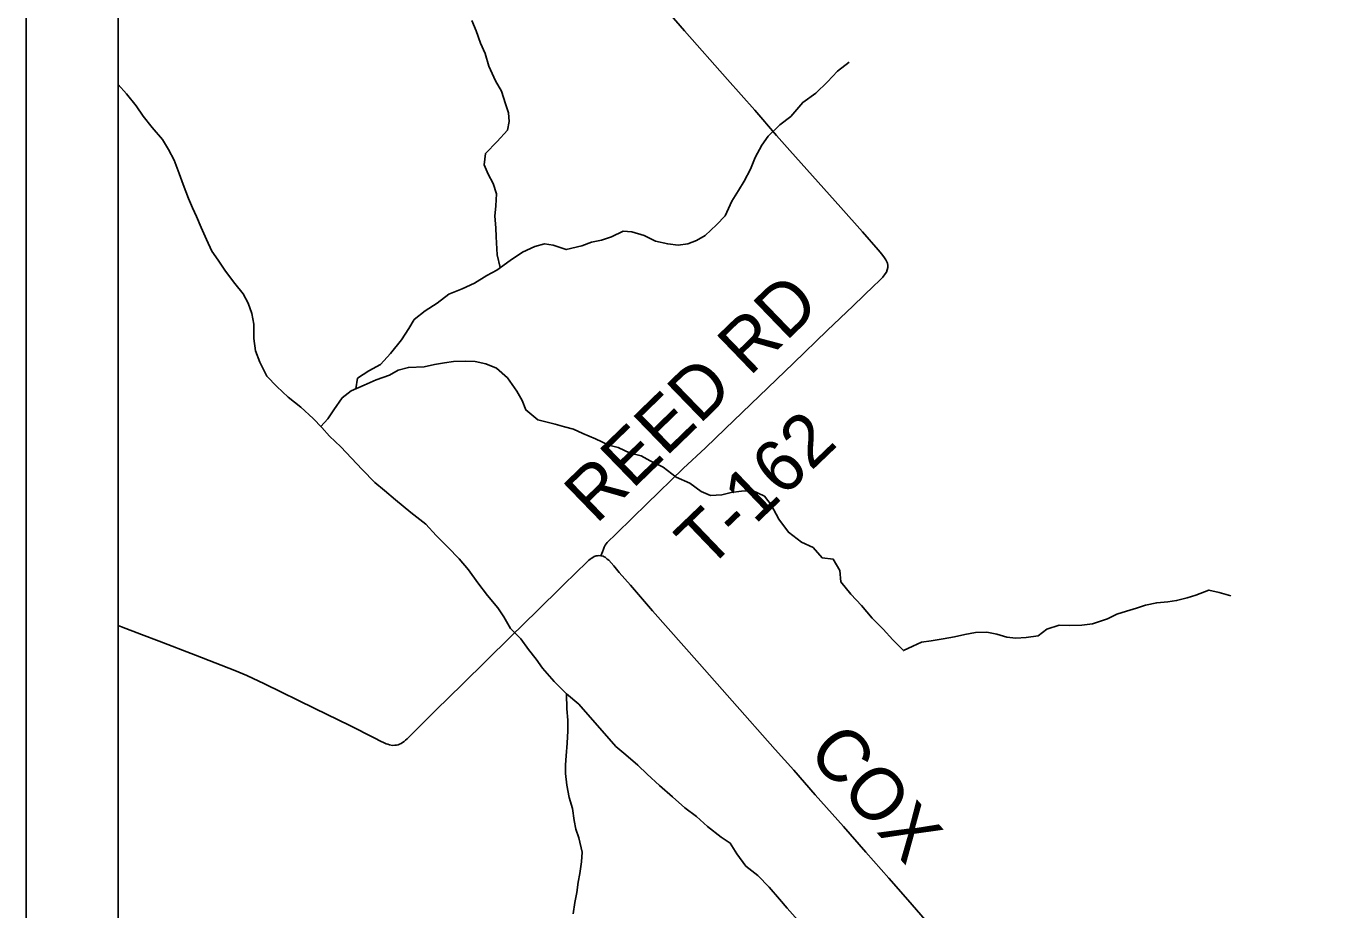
# Model space of a CAD drawing. Extents: x 0 to 34, y 0 to 22.
# Drawn here: x 2 to 3.432, y 19.235 to 20.196 of the extents above; entities that cross this region are included whole.
import ezdxf

# ---------------------------------------------------------------- set-up
doc = ezdxf.new("R2010")
doc.units = 0
for name, color, linetype in [('Default', 7, 'Continuous'), ('GM_X_County_Road', 7, 'Continuous'), ('GM_X_County_Road_Text', 7, 'Continuous'), ('GM_X_Major_River', 7, 'Continuous'), ('GM_X_Minor_River', 7, 'Continuous'), ('GM_X_Township_Road', 7, 'Continuous'), ('GM_X_Township_Road_Text', 7, 'Continuous'), ('SH_Cut_Line', 7, 'Continuous'), ('SH_Data', 7, 'Continuous')]:
    doc.layers.add(name, color=color, linetype=linetype)

msp = doc.modelspace()

# ---------------------------------------------------------------- linework, layer by layer
at = {"layer": 'Default'}
msp.add_lwpolyline([(6.6858, 19.0362), (6.6949, 19.1537), (6.8302, 20.9), (3.1229, 20.9), (2.9275, 20.8467), (2.2946, 20.6707), (2.1, 20.6202), (2.1, 17.1279), (2.1211, 17.1003), (3.2076, 15.5689), (3.4902, 15.1704), (4.0558, 14.3671), (4.1658, 14.2105), (4.302, 14.3105), (5.6165, 15.2674), (6.0871, 15.6176), (6.2834, 15.7529), (6.4392, 15.8657), (6.5428, 17.1931), (6.5451, 17.2211), (6.6309, 18.3364), (6.6363, 18.3979), (6.6654, 18.7733)], dxfattribs=at)
at = {"layer": 'GM_X_County_Road'}
for points in [[(2.6248, 19.6198), (2.6226, 19.62), (2.6211, 19.6199), (2.6199, 19.6197), (2.6188, 19.6194), (2.6177, 19.6189), (2.616, 19.618), (2.6142, 19.6168), (2.6132, 19.6161), (2.6119, 19.615), (2.6101, 19.6134), (2.6073, 19.6108), (2.5998, 19.6034), (2.5821, 19.5859), (2.556, 19.5602), (2.5265, 19.5317), (2.5004, 19.5059), (2.4743, 19.4802), (2.4454, 19.452), (2.4182, 19.4247), (2.4142, 19.4207), (2.4123, 19.4191), (2.4108, 19.4178), (2.409, 19.4167), (2.4075, 19.4157), (2.4058, 19.4149), (2.4043, 19.4143), (2.4027, 19.4139), (2.4008, 19.4136), (2.3982, 19.4135), (2.3949, 19.4141), (2.393, 19.4147), (2.3913, 19.4153), (2.3886, 19.4166), (2.3861, 19.4178), (2.3784, 19.4217), (2.3517, 19.435), (2.3138, 19.4538), (2.2592, 19.4806), (2.24, 19.4895), (2.2269, 19.4949), (2.1841, 19.5118), (2.1446, 19.5268), (2.1254, 19.534), (2.1034, 19.5426), (2.1, 19.5439)], [(2.9823, 19.2184), (2.9586, 19.2455), (2.9382, 19.2689), (2.9131, 19.2974), (2.8886, 19.3254), (2.8581, 19.3599), (2.8346, 19.3864), (2.8144, 19.4091), (2.7675, 19.4621), (2.732, 19.5021), (2.6811, 19.56), (2.6571, 19.5877), (2.6449, 19.6018), (2.6389, 19.6089), (2.6336, 19.6149), (2.6319, 19.6163), (2.6308, 19.6172), (2.6294, 19.6182), (2.6285, 19.6186), (2.6273, 19.6193), (2.6261, 19.6196), (2.6248, 19.6198)]]:
    msp.add_lwpolyline(points, dxfattribs=at)
at = {"layer": 'GM_X_Major_River'}
msp.add_lwpolyline([(2.1, 20.1327), (2.1089, 20.1225), (2.1195, 20.1092), (2.127, 20.0981), (2.1368, 20.0859), (2.1481, 20.0726), (2.1545, 20.0619), (2.1609, 20.0501), (2.1662, 20.0357), (2.1706, 20.0239), (2.1763, 20.0087), (2.1808, 19.9984), (2.1849, 19.9889), (2.1901, 19.9771), (2.1958, 19.9638), (2.2018, 19.9512), (2.2085, 19.9413), (2.2165, 19.9295), (2.2266, 19.9162), (2.2357, 19.9047), (2.2413, 19.8945), (2.2454, 19.8834), (2.2473, 19.872), (2.2476, 19.8561), (2.2494, 19.8428), (2.2539, 19.8303), (2.2614, 19.8154), (2.2724, 19.804), (2.2848, 19.7925), (2.2984, 19.7815), (2.312, 19.7692), (2.3215, 19.7593), (2.3298, 19.7498), (2.3419, 19.7383), (2.3536, 19.7261), (2.3653, 19.7136), (2.3789, 19.6994), (2.3894, 19.6907), (2.4015, 19.6807), (2.4182, 19.667), (2.4344, 19.6544), (2.4458, 19.6418), (2.4586, 19.6292), (2.4707, 19.6166), (2.4809, 19.6044), (2.491, 19.5903), (2.5016, 19.5766), (2.5129, 19.5633), (2.5193, 19.5534), (2.5265, 19.5408), (2.5378, 19.5294), (2.5461, 19.5179), (2.5544, 19.5073), (2.5615, 19.4977), (2.574, 19.4832), (2.5876, 19.4695), (2.6008, 19.4584)], dxfattribs=at)
at = {"layer": 'GM_X_Minor_River'}
for points in [[(2.5154, 19.9333), (2.5121, 19.9472), (2.5109, 19.967), (2.5106, 19.9765), (2.5096, 19.9895), (2.5105, 20.0005), (2.5114, 20.0137), (2.5078, 20.0248), (2.5022, 20.0351), (2.4981, 20.0451), (2.4994, 20.0576), (2.5121, 20.0704), (2.5233, 20.0828), (2.5253, 20.0922), (2.5243, 20.1018), (2.5213, 20.1117), (2.5169, 20.1254), (2.5102, 20.1365), (2.5032, 20.1525), (2.4992, 20.1663), (2.494, 20.1777), (2.4892, 20.1911), (2.4844, 20.2021)], [(2.3584, 19.8016), (2.3603, 19.8129), (2.3725, 19.8211), (2.3852, 19.8278), (2.396, 19.8399), (2.4079, 19.8546), (2.4161, 19.867), (2.4219, 19.8768), (2.4338, 19.8862), (2.4468, 19.8948), (2.4595, 19.9045), (2.474, 19.9101), (2.4874, 19.9164), (2.5008, 19.9246), (2.5116, 19.9305), (2.5261, 19.941), (2.5396, 19.95), (2.553, 19.9563), (2.5637, 19.9592), (2.5731, 19.9576), (2.5872, 19.9529), (2.604, 19.9572), (2.6147, 19.9609), (2.6257, 19.9631), (2.6364, 19.9667), (2.649, 19.9731), (2.6585, 19.9722), (2.6718, 19.9682), (2.6843, 19.962), (2.6976, 19.9592), (2.709, 19.9579), (2.7193, 19.9594), (2.7288, 19.9627), (2.7384, 19.9683), (2.7507, 19.9799), (2.76, 19.9897), (2.7674, 20.0055), (2.7747, 20.0172), (2.7806, 20.0274), (2.7876, 20.0403), (2.7927, 20.0531), (2.8001, 20.0664), (2.807, 20.0762), (2.8194, 20.0886), (2.8313, 20.0979), (2.8444, 20.113), (2.8586, 20.1231), (2.8713, 20.1355), (2.8821, 20.1471), (2.8951, 20.1569)], [(2.3204, 19.7605), (2.3278, 19.7688), (2.3344, 19.7786), (2.3436, 19.7918), (2.3532, 19.7993), (2.3674, 19.8056), (2.3804, 19.8112), (2.3949, 19.8163), (2.4045, 19.8219), (2.4156, 19.8248), (2.4327, 19.8254), (2.4441, 19.8279), (2.4548, 19.8297), (2.4647, 19.8311), (2.4777, 19.8314), (2.4883, 19.8312), (2.4997, 19.8288), (2.5114, 19.8241), (2.5235, 19.8134), (2.5336, 19.7988), (2.5392, 19.7889), (2.5432, 19.7786), (2.5564, 19.7678), (2.575, 19.763), (2.5852, 19.7602), (2.5951, 19.7575), (2.6053, 19.7528), (2.6189, 19.7469), (2.6337, 19.7403), (2.6436, 19.7375), (2.6568, 19.7313), (2.6686, 19.7285), (2.6784, 19.7231), (2.6928, 19.7161), (2.7067, 19.7053), (2.7215, 19.6987), (2.7339, 19.6898), (2.7441, 19.6855), (2.7563, 19.6861), (2.7666, 19.6887), (2.7777, 19.6901), (2.7899, 19.6907), (2.8027, 19.6848), (2.8102, 19.6752), (2.8184, 19.6596), (2.8289, 19.6454), (2.8432, 19.6346), (2.8557, 19.6288), (2.8655, 19.6176), (2.8776, 19.616), (2.8847, 19.6037), (2.8857, 19.5916), (2.8966, 19.5781), (2.9082, 19.5659), (2.9198, 19.552), (2.9319, 19.5401), (2.9424, 19.5282), (2.954, 19.5167), (2.964, 19.5215), (2.9735, 19.526), (2.9842, 19.5274), (2.9972, 19.5295), (3.0094, 19.5317), (3.0208, 19.5342), (3.0323, 19.5363), (3.0448, 19.5366), (3.0555, 19.5346), (3.0664, 19.5314), (3.0763, 19.5301), (3.0874, 19.5308), (3.1003, 19.5329), (3.1099, 19.54), (3.1233, 19.5444), (3.1343, 19.5439), (3.148, 19.5442), (3.1595, 19.5459), (3.1759, 19.5514), (3.1862, 19.5563), (3.1965, 19.5596), (3.2076, 19.5629), (3.2171, 19.5662), (3.2294, 19.5687), (3.2415, 19.5697), (3.2511, 19.5711), (3.2625, 19.574), (3.2721, 19.577), (3.2862, 19.5825), (3.2972, 19.5797), (3.3101, 19.5761)], [(2.5876, 19.4695), (2.588, 19.4532), (2.589, 19.441), (2.5889, 19.4292), (2.5883, 19.416), (2.587, 19.4023), (2.5865, 19.3924), (2.5864, 19.3829), (2.5878, 19.3704), (2.5903, 19.3567), (2.594, 19.3448), (2.5957, 19.3319), (2.5975, 19.3224), (2.6008, 19.3128), (2.6044, 19.2972), (2.6039, 19.287), (2.6019, 19.2741), (2.6002, 19.2646), (2.5986, 19.2536), (2.5965, 19.2426), (2.5949, 19.2301)], [(2.6008, 19.4584), (2.6412, 19.4123), (2.6521, 19.4031), (2.6649, 19.3919), (2.6751, 19.3823), (2.6886, 19.37), (2.7029, 19.3577), (2.7161, 19.3457), (2.7289, 19.3361), (2.741, 19.3253), (2.7557, 19.3138), (2.7655, 19.3072), (2.7726, 19.2957), (2.7827, 19.2823), (2.7955, 19.2719), (2.8079, 19.2592), (2.8191, 19.2462), (2.8274, 19.2366), (2.839, 19.2235)]]:
    msp.add_lwpolyline(points, dxfattribs=at)
at = {"layer": 'GM_X_Township_Road'}
msp.add_lwpolyline([(2.6248, 19.6198), (2.6265, 19.6241), (2.6277, 19.6272), (2.6285, 19.6292), (2.6296, 19.6315), (2.6316, 19.6342), (2.6414, 19.6438), (2.6592, 19.6611), (2.6747, 19.6763), (2.7145, 19.7147), (2.7385, 19.7373), (2.7599, 19.7581), (2.8343, 19.8295), (2.871, 19.8649), (2.8993, 19.8919), (2.9222, 19.9138), (2.9267, 19.9181), (2.9294, 19.9208), (2.9315, 19.923), (2.9342, 19.9265), (2.9354, 19.9285), (2.9364, 19.9309), (2.9368, 19.9336), (2.9368, 19.9355), (2.9365, 19.9382), (2.9357, 19.9403), (2.9349, 19.9419), (2.9335, 19.9439), (2.9306, 19.948), (2.9266, 19.9528), (2.9093, 19.9723), (2.8857, 19.9987), (2.8489, 20.04), (2.8304, 20.0609), (2.8159, 20.0772), (2.7925, 20.1046), (2.7627, 20.1379), (2.7158, 20.191), (2.6585, 20.2573)], dxfattribs=at)
at = {"layer": 'SH_Cut_Line'}
msp.add_lwpolyline([(6.6858, 19.0362), (6.6949, 19.1537), (6.8302, 20.9), (2.1, 20.9), (2.1, 14.1), (4.022, 14.1), (4.1658, 14.2105), (4.302, 14.3105), (5.6165, 15.2674), (6.0871, 15.6176), (6.2834, 15.7529), (6.4392, 15.8657), (6.5428, 17.1931), (6.5451, 17.2211), (6.6309, 18.3364), (6.6363, 18.3979), (6.6654, 18.7733)], dxfattribs=at)
at = {"layer": 'SH_Data'}
for p, q in [((2, 21), (2, 14)), ((2.1, 20.9), (2.1, 14.1))]:
    msp.add_line(p, q, dxfattribs=at)

# ---------------------------------------------------------------- texts
at = {"layer": 'GM_X_County_Road_Text'}
msp.add_text('COX', height=0.05682, rotation=311.5589, dxfattribs=at).set_placement((2.8481, 19.405))
at = {"layer": 'GM_X_Township_Road_Text'}
for s, rotation, p in [('RD', 43.9462, (2.7864, 19.8142)), ('REED', 44.074, (2.6197, 19.6533)), ('T-162', 43.8153, (2.7406, 19.6033))]:
    msp.add_text(s, height=0.05682, rotation=rotation, dxfattribs=at).set_placement(p)

doc.saveas('drawing.dxf')
